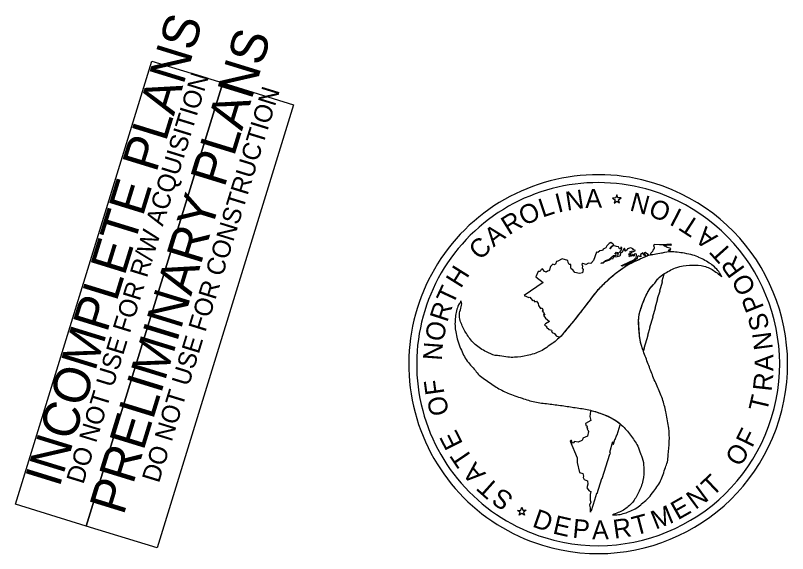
# Model space of a CAD drawing. Extents: x 1347947 to 1350662, y 1027710 to 1030532.
# Drawn here: x 1349312.6 to 1349557.4, y 1030182.8 to 1030353.4 of the extents above; entities that cross this region are included whole.
import ezdxf

# ---------------------------------------------------------------- set-up
doc = ezdxf.new("R2010")
doc.units = 0
for name, color, linetype in [('Old_Level_20', 7, 'Continuous'), ('Sheet Sticker Incomplete CELL', 7, 'Continuous'), ('Sheet Sticker Preliminary CELL', 7, 'Continuous'), ('Sheet Title CELL', 7, 'Continuous')]:
    doc.layers.add(name, color=color, linetype=linetype)

msp = doc.modelspace()

# ---------------------------------------------------------------- linework, layer by layer
at = {"layer": 'Old_Level_20'}
for p, q in [((1349520.2, 1030280.92), (1349517.93, 1030280.66)), ((1349520.59, 1030280.8), (1349520.2, 1030280.92)), ((1349514.56, 1030278.57), (1349513.96, 1030277.91)), ((1349514.68, 1030278.96), (1349514.56, 1030278.57)), ((1349514.95, 1030279.36), (1349514.68, 1030278.96)), ((1349515.06, 1030280.74), (1349514.84, 1030280.22)), ((1349514.84, 1030280.22), (1349515.11, 1030279.99)), ((1349515.06, 1030279.47), (1349514.95, 1030279.36)), ((1349516.78, 1030280.7), (1349515.06, 1030280.74)), ((1349515.12, 1030279.73), (1349515.06, 1030279.47)), ((1349515.11, 1030279.99), (1349515.12, 1030279.73)), ((1349517.93, 1030280.66), (1349516.78, 1030280.7)), ((1349518.12, 1030280.43), (1349518.16, 1030280.56)), ((1349518.21, 1030280.26), (1349518.12, 1030280.43)), ((1349518.16, 1030280.56), (1349520.16, 1030280.71)), ((1349518.65, 1030280.12), (1349518.21, 1030280.26)), ((1349518.85, 1030280.23), (1349518.65, 1030280.12)), ((1349519.03, 1030279.89), (1349518.85, 1030280.23)), ((1349520.33, 1030279.49), (1349519.03, 1030279.89)), ((1349519.63, 1030278.42), (1349519.1, 1030278.33)), ((1349519.5, 1030278.92), (1349520.08, 1030279.23)), ((1349519.85, 1030278.87), (1349519.5, 1030278.92)), ((1349519.99, 1030278.48), (1349519.63, 1030278.42)), ((1349520.14, 1030278.98), (1349519.85, 1030278.87)), ((1349519.99, 1030278.48), (1349520.14, 1030278.98)), ((1349520.08, 1030279.23), (1349520.24, 1030279.21)), ((1349520.16, 1030280.71), (1349520.34, 1030280.56)), ((1349520.24, 1030279.21), (1349520.33, 1030279.49)), ((1349520.34, 1030280.56), (1349520.5, 1030280.52)), ((1349520.5, 1030280.52), (1349520.59, 1030280.8)), ((1349485.87, 1030276.25), (1349484.56, 1030275.49)), ((1349487.76, 1030275.67), (1349485.87, 1030276.25)), ((1349496.77, 1030278.35), (1349495.81, 1030275.69)), ((1349511.75, 1030276.66), (1349510.1, 1030275.9)), ((1349511.56, 1030278.13), (1349510.8, 1030277.6)), ((1349510.8, 1030277.6), (1349510.9, 1030276.83)), ((1349511.68, 1030277.53), (1349511.56, 1030278.13)), ((1349512.39, 1030277.14), (1349511.68, 1030277.53)), ((1349512.41, 1030276.99), (1349511.75, 1030276.66)), ((1349512.19, 1030278.25), (1349511.87, 1030278.12)), ((1349511.87, 1030278.12), (1349512.39, 1030277.14)), ((1349513.29, 1030277.49), (1349512.19, 1030278.25)), ((1349512.41, 1030276.99), (1349512.96, 1030277.2)), ((1349512.95, 1030277.22), (1349513.02, 1030277.45)), ((1349512.96, 1030277.2), (1349512.95, 1030277.22)), ((1349513.02, 1030277.45), (1349513.29, 1030277.49)), ((1349514.05, 1030277.56), (1349513.92, 1030277.4)), ((1349514.13, 1030277.44), (1349513.92, 1030277.4)), ((1349513.96, 1030277.91), (1349514.05, 1030277.56)), ((1349514.63, 1030277.52), (1349514.13, 1030277.44)), ((1349515.18, 1030277.62), (1349514.63, 1030277.52)), ((1349515.65, 1030277.71), (1349515.18, 1030277.62)), ((1349516.23, 1030277.81), (1349515.65, 1030277.71)), ((1349516.85, 1030277.92), (1349516.23, 1030277.81)), ((1349517.63, 1030278.06), (1349516.85, 1030277.92)), ((1349518.37, 1030278.2), (1349517.63, 1030278.06)), ((1349519.1, 1030278.33), (1349518.37, 1030278.2)), ((1349482.24, 1030273.77), (1349481.95, 1030272.75)), ((1349482.96, 1030274.54), (1349482.24, 1030273.77)), ((1349483.5, 1030274.37), (1349482.96, 1030274.54)), ((1349483.8, 1030274.59), (1349483.5, 1030274.37)), ((1349484.09, 1030275.35), (1349483.8, 1030274.59)), ((1349484.56, 1030275.49), (1349484.09, 1030275.35)), ((1349487.82, 1030275.03), (1349487.76, 1030275.67)), ((1349488.13, 1030274.45), (1349487.82, 1030275.03)), ((1349488.68, 1030274.39), (1349488.13, 1030274.45)), ((1349488.65, 1030273.58), (1349488.68, 1030274.39)), ((1349488.8, 1030273.05), (1349488.65, 1030273.58)), ((1349492.48, 1030274.76), (1349492.12, 1030274.5)), ((1349492.12, 1030274.5), (1349492.38, 1030273.88)), ((1349492.38, 1030273.88), (1349492.24, 1030273.24)), ((1349493.16, 1030274.55), (1349492.48, 1030274.76)), ((1349493.36, 1030274.37), (1349493.16, 1030274.55)), ((1349494.3, 1030274.85), (1349493.36, 1030274.37)), ((1349494.99, 1030274.78), (1349494.3, 1030274.85)), ((1349495.81, 1030275.69), (1349494.99, 1030274.78)), ((1349506.64, 1030274.18), (1349505.12, 1030273.22)), ((1349508.75, 1030275.26), (1349506.64, 1030274.18)), ((1349510.1, 1030275.9), (1349508.75, 1030275.26)), ((1349478.3, 1030272.25), (1349477.58, 1030270.55)), ((1349478.93, 1030272.26), (1349478.3, 1030272.25)), ((1349479.24, 1030272.81), (1349478.93, 1030272.26)), ((1349479.71, 1030273.04), (1349479.24, 1030272.81)), ((1349479.91, 1030272.75), (1349479.71, 1030273.04)), ((1349480.15, 1030272.62), (1349479.91, 1030272.75)), ((1349480.13, 1030272.29), (1349480.15, 1030272.62)), ((1349480.8, 1030271.97), (1349480.13, 1030272.29)), ((1349481.3, 1030272.38), (1349480.8, 1030271.97)), ((1349481.7, 1030272.48), (1349481.3, 1030272.38)), ((1349481.95, 1030272.75), (1349481.7, 1030272.48)), ((1349489.32, 1030272.78), (1349488.8, 1030273.05)), ((1349489.97, 1030271.95), (1349489.32, 1030272.78)), ((1349491.4, 1030271.62), (1349489.97, 1030271.95)), ((1349492.33, 1030271.77), (1349491.4, 1030271.62)), ((1349492.24, 1030273.24), (1349492.56, 1030272.89)), ((1349492.56, 1030272.89), (1349492.33, 1030271.77)), ((1349503.05, 1030271.66), (1349500.54, 1030269.54)), ((1349505.12, 1030273.22), (1349503.05, 1030271.66)), ((1349516.82, 1030270.44), (1349517.73, 1030271.15)), ((1349517.62, 1030269.31), (1349518.26, 1030271.41)), ((1349517.73, 1030271.15), (1349518.16, 1030271.44)), ((1349518.15, 1030271.42), (1349518.16, 1030271.44)), ((1349518.26, 1030271.41), (1349518.15, 1030271.42)), ((1349479.91, 1030268.69), (1349473.92, 1030264.58)), ((1349477.58, 1030270.55), (1349479.91, 1030268.69)), ((1349500.54, 1030269.54), (1349498.69, 1030267.86)), ((1349515.3, 1030268.56), (1349515.95, 1030269.49)), ((1349515.95, 1030269.49), (1349516.82, 1030270.44)), ((1349516.87, 1030266.14), (1349517.7, 1030268.95)), ((1349517.73, 1030269.31), (1349517.62, 1030269.31)), ((1349517.63, 1030268.97), (1349517.73, 1030269.31)), ((1349517.7, 1030268.95), (1349517.63, 1030268.97)), ((1349497.35, 1030266.49), (1349495.63, 1030264.4)), ((1349498.69, 1030267.86), (1349497.35, 1030266.49)), ((1349513.19, 1030265.93), (1349513.85, 1030266.93)), ((1349513.85, 1030266.93), (1349514.48, 1030267.64)), ((1349514.48, 1030267.64), (1349515.3, 1030268.56)), ((1349473.92, 1030264.58), (1349475.31, 1030264.01)), ((1349475.31, 1030264.01), (1349475.72, 1030264.05)), ((1349475.72, 1030264.05), (1349476.48, 1030263.02)), ((1349495.63, 1030264.4), (1349493.59, 1030261.74)), ((1349512.03, 1030263.51), (1349512.56, 1030264.68)), ((1349512.56, 1030264.68), (1349513.19, 1030265.93)), ((1349516.19, 1030263.65), (1349516.95, 1030266.11)), ((1349516.95, 1030266.11), (1349516.87, 1030266.14)), ((1349476.48, 1030263.02), (1349476.79, 1030263.1)), ((1349476.79, 1030263.1), (1349477.25, 1030262.56)), ((1349477.25, 1030262.56), (1349477.76, 1030262.83)), ((1349477.76, 1030262.83), (1349478.27, 1030262.08)), ((1349478.27, 1030262.08), (1349478.43, 1030261.49)), ((1349478.43, 1030261.49), (1349479.06, 1030260.5)), ((1349493.59, 1030261.74), (1349491.72, 1030259.29)), ((1349511.04, 1030260.92), (1349511.4, 1030261.93)), ((1349511.4, 1030261.93), (1349512.03, 1030263.51)), ((1349515.4, 1030260.63), (1349516.29, 1030263.62)), ((1349516.29, 1030263.62), (1349516.19, 1030263.65)), ((1349479.06, 1030260.5), (1349479.43, 1030260.69)), ((1349479.43, 1030260.69), (1349479.92, 1030259.98)), ((1349479.92, 1030259.98), (1349479.6, 1030259.76)), ((1349479.6, 1030259.76), (1349479.99, 1030259.19)), ((1349479.99, 1030259.19), (1349480.43, 1030258.49)), ((1349491.72, 1030259.29), (1349490, 1030257.14)), ((1349510.37, 1030258.73), (1349510.66, 1030259.78)), ((1349510.66, 1030259.78), (1349511.04, 1030260.92)), ((1349514.65, 1030257.91), (1349515.48, 1030260.61)), ((1349515.48, 1030260.61), (1349515.4, 1030260.63)), ((1349480.43, 1030258.49), (1349480, 1030258.59)), ((1349480, 1030258.59), (1349480.14, 1030258.21)), ((1349480.14, 1030258.21), (1349480.6, 1030257.47)), ((1349480.6, 1030257.47), (1349481.88, 1030256.37)), ((1349481.88, 1030256.37), (1349480.66, 1030255.63)), ((1349490, 1030257.14), (1349488.28, 1030255)), ((1349510.15, 1030256.8), (1349510.19, 1030257.66)), ((1349510.2, 1030255.89), (1349510.15, 1030256.8)), ((1349510.19, 1030257.66), (1349510.37, 1030258.73)), ((1349513.74, 1030254.59), (1349514.75, 1030257.88)), ((1349514.75, 1030257.88), (1349514.65, 1030257.91)), ((1349480.66, 1030255.63), (1349480.31, 1030255.34)), ((1349480.31, 1030255.34), (1349480.65, 1030254.98)), ((1349480.65, 1030254.98), (1349480.99, 1030254.88)), ((1349480.99, 1030254.88), (1349480.93, 1030254.58)), ((1349480.93, 1030254.58), (1349481.76, 1030253.87)), ((1349488.28, 1030255), (1349486.6, 1030252.96)), ((1349510.26, 1030254.85), (1349510.2, 1030255.89)), ((1349510.32, 1030253.94), (1349510.26, 1030254.85)), ((1349510.38, 1030252.97), (1349510.32, 1030253.94)), ((1349513.07, 1030252.07), (1349513.85, 1030254.58)), ((1349513.85, 1030254.58), (1349513.74, 1030254.59)), ((1349481.76, 1030253.87), (1349482.63, 1030253.64)), ((1349482.63, 1030253.64), (1349482.49, 1030253.37)), ((1349482.49, 1030253.37), (1349482.76, 1030252.88)), ((1349482.76, 1030252.88), (1349483.51, 1030252.54)), ((1349483.51, 1030252.54), (1349484.05, 1030251.81)), ((1349484.05, 1030251.81), (1349484.73, 1030251.51)), ((1349484.73, 1030251.51), (1349484.94, 1030251.17)), ((1349485.55, 1030251.77), (1349484.94, 1030251.17)), ((1349486.6, 1030252.96), (1349485.55, 1030251.77)), ((1349510.46, 1030251.89), (1349510.38, 1030252.97)), ((1349510.6, 1030250.7), (1349510.46, 1030251.89)), ((1349511.92, 1030247.96), (1349513.15, 1030252.04)), ((1349513.15, 1030252.04), (1349513.07, 1030252.07)), ((1349510.8, 1030249.73), (1349510.6, 1030250.7)), ((1349511.05, 1030248.81), (1349510.8, 1030249.73)), ((1349511.4, 1030247.73), (1349511.05, 1030248.81)), ((1349511.69, 1030246.92), (1349511.4, 1030247.73)), ((1349511.69, 1030246.92), (1349512, 1030247.94)), ((1349512, 1030247.94), (1349511.92, 1030247.96)), ((1349494.9, 1030227.92), (1349494.73, 1030226.27)), ((1349495.02, 1030227.85), (1349494.9, 1030227.92)), ((1349495.03, 1030228.21), (1349495.02, 1030227.85)), ((1349495.03, 1030228.21), (1349495.83, 1030228)), ((1349495.83, 1030228), (1349497.05, 1030227.6)), ((1349497.05, 1030227.6), (1349497.89, 1030227.31)), ((1349497.89, 1030227.31), (1349499.34, 1030226.79)), ((1349494.97, 1030225), (1349493.29, 1030224.07)), ((1349494.73, 1030226.27), (1349494.97, 1030225)), ((1349499.34, 1030226.79), (1349500.89, 1030226.09)), ((1349500.89, 1030226.09), (1349502.41, 1030225.27)), ((1349502.41, 1030225.27), (1349503.24, 1030224.74)), ((1349503.24, 1030224.74), (1349504.06, 1030224.13)), ((1349493.29, 1030224.07), (1349493.46, 1030223.51)), ((1349493.46, 1030223.51), (1349493.83, 1030223.16)), ((1349493.83, 1030223.16), (1349493.74, 1030222.77)), ((1349493.74, 1030222.77), (1349493.94, 1030222.48)), ((1349493.94, 1030222.48), (1349493.87, 1030222.19)), ((1349493.87, 1030222.19), (1349494.08, 1030222.04)), ((1349503.31, 1030220.45), (1349504.28, 1030223.61)), ((1349504.06, 1030224.13), (1349504.45, 1030223.8)), ((1349504.28, 1030223.61), (1349504.39, 1030223.58)), ((1349504.39, 1030223.58), (1349504.45, 1030223.8)), ((1349493.9, 1030220.05), (1349492.49, 1030219.35)), ((1349494.22, 1030221.46), (1349493.9, 1030220.05)), ((1349494.08, 1030222.04), (1349494.22, 1030221.46)), ((1349502.76, 1030218.94), (1349503.23, 1030220.47)), ((1349503.23, 1030220.47), (1349503.31, 1030220.45)), ((1349488.62, 1030218.7), (1349488.42, 1030218.42)), ((1349488.42, 1030218.42), (1349490.68, 1030213.12)), ((1349488.92, 1030218.63), (1349488.62, 1030218.7)), ((1349489.1, 1030217.95), (1349488.92, 1030218.63)), ((1349489.44, 1030217.85), (1349489.1, 1030217.95)), ((1349489.82, 1030218.35), (1349489.44, 1030217.85)), ((1349491.01, 1030218.13), (1349489.82, 1030218.35)), ((1349492.14, 1030218.69), (1349491.01, 1030218.13)), ((1349492.32, 1030218.81), (1349492.14, 1030218.69)), ((1349492.49, 1030219.35), (1349492.32, 1030218.81)), ((1349501.91, 1030217.93), (1349502.09, 1030217.5)), ((1349502.09, 1030217.5), (1349502.2, 1030217.49)), ((1349502.2, 1030217.49), (1349502.66, 1030219)), ((1349502.66, 1030219), (1349502.76, 1030218.94)), ((1349490.68, 1030213.12), (1349490.71, 1030211.72)), ((1349490.71, 1030211.72), (1349491.39, 1030208.5)), ((1349491.39, 1030208.5), (1349492.45, 1030208.15)), ((1349492.45, 1030208.15), (1349492.72, 1030207.36)), ((1349492.72, 1030207.36), (1349492.55, 1030206.93)), ((1349492.55, 1030206.93), (1349492.85, 1030206.32)), ((1349492.85, 1030206.32), (1349493.92, 1030205.91)), ((1349493.92, 1030205.91), (1349494.05, 1030204.85)), ((1349494.05, 1030204.85), (1349493.77, 1030203.6)), ((1349493.77, 1030203.6), (1349494.48, 1030202.67)), ((1349494.48, 1030202.67), (1349495.04, 1030202.47)), ((1349494.8, 1030201.58), (1349494.76, 1030199.69)), ((1349495.04, 1030202.47), (1349494.8, 1030201.58)), ((1349495.05, 1030199.06), (1349494.6, 1030198.15)), ((1349494.6, 1030198.15), (1349494.75, 1030197.28)), ((1349494.76, 1030199.69), (1349495.05, 1030199.06)), ((1349494.75, 1030197.28), (1349494.75, 1030196.34)), ((1349494.75, 1030196.34), (1349494.87, 1030195.91))]:
    msp.add_line(p, q, dxfattribs=at)
for points in [[(1349504.16, 1030277.06), (1349503.38, 1030276.85), (1349502.24, 1030276.75), (1349501.84, 1030276.1), (1349501.32, 1030276.24), (1349500.93, 1030275.81), (1349499.37, 1030275.27), (1349498.96, 1030274.86), (1349498.16, 1030274.77), (1349498.44, 1030275.02), (1349498.93, 1030275.04), (1349499.63, 1030275.73), (1349499.97, 1030275.66), (1349500.16, 1030275.88), (1349500.63, 1030275.94), (1349502.15, 1030277.28), (1349502.72, 1030277.31), (1349503.04, 1030277.49), (1349503.39, 1030277.44), (1349503.83, 1030277.59), (1349503.6, 1030277.94), (1349503.16, 1030278.08), (1349502.59, 1030277.77), (1349503.19, 1030278.35), (1349503.86, 1030278.12), (1349504.73, 1030279.13), (1349504.88, 1030279.88), (1349504.54, 1030279.9), (1349504.4, 1030279.43), (1349504.11, 1030279.41), (1349503.73, 1030280.01), (1349503.16, 1030280.1), (1349502.54, 1030280.31), (1349501.77, 1030280.21), (1349501.05, 1030279.44), (1349501.65, 1030280.28), (1349502.29, 1030280.68), (1349501.8, 1030281.05), (1349501.32, 1030281.43), (1349500.81, 1030281.05), (1349500.07, 1030280.31), (1349499.8, 1030279.71), (1349498.91, 1030279.3), (1349498.78, 1030278.98), (1349498.54, 1030278.85), (1349497.84, 1030278.78), (1349497.23, 1030278.2), (1349496.77, 1030278.35)], [(1349510.9, 1030276.83), (1349510, 1030277.22), (1349509.84, 1030276.99), (1349509.75, 1030276.31), (1349508.69, 1030275.47), (1349505.8, 1030274.2), (1349505.3, 1030274.13), (1349505.06, 1030273.92), (1349504.68, 1030273.98), (1349504.68, 1030274.15), (1349505.24, 1030274.32), (1349508.62, 1030275.97), (1349509.03, 1030276.3), (1349509.34, 1030276.29), (1349509.45, 1030277.73), (1349509.05, 1030277.83), (1349508.78, 1030277.68), (1349508.75, 1030277.24), (1349508.4, 1030277.12), (1349508.39, 1030277.63), (1349507.79, 1030277.05), (1349507.1, 1030276.95), (1349507.65, 1030277.35), (1349507.79, 1030277.7), (1349507.4, 1030277.74), (1349507.08, 1030277.44), (1349507.28, 1030278), (1349507.6, 1030278.02), (1349508.11, 1030278.29), (1349507.38, 1030278.48), (1349507.85, 1030278.62), (1349508.29, 1030278.49), (1349509.16, 1030278.93), (1349508.68, 1030279.11), (1349508.33, 1030278.99), (1349508.45, 1030279.38), (1349507.58, 1030279.7), (1349506.67, 1030279.41), (1349506.54, 1030279.08), (1349506.03, 1030278.64), (1349505.75, 1030278.82), (1349505.85, 1030279.15), (1349505.68, 1030279.63), (1349505.23, 1030279.09), (1349504.96, 1030278.29), (1349504.56, 1030278.27), (1349504.16, 1030277.06)], [(1349494.87, 1030195.91), (1349495.05, 1030196.48), (1349495.18, 1030196.44), (1349496.23, 1030199.86), (1349496.3, 1030199.81), (1349496.95, 1030201.91), (1349497.05, 1030201.88), (1349498.52, 1030206.65), (1349498.62, 1030206.62), (1349501.01, 1030214.37), (1349501.11, 1030214.31), (1349501.23, 1030214.73), (1349501.13, 1030214.76), (1349501.16, 1030214.86), (1349500.98, 1030214.92), (1349502.02, 1030218.29)]]:
    msp.add_lwpolyline(points, dxfattribs=at)
at = {"layer": 'Sheet Sticker Incomplete CELL'}
msp.add_lwpolyline([(1349335.04, 1030191.51), (1349312.58, 1030198.42), (1349355.85, 1030338.91), (1349378.3, 1030332)], close=True, dxfattribs=at)
at = {"layer": 'Sheet Sticker Preliminary CELL'}
msp.add_lwpolyline([(1349357.5, 1030184.59), (1349335.04, 1030191.51), (1349378.3, 1030332), (1349400.76, 1030325.08)], close=True, dxfattribs=at)
at = {"layer": 'Sheet Title CELL'}
for p, q in [((1349515, 1030300.24), (1349515, 1030300.24)), ((1349502.94, 1030295.54), (1349501.92, 1030295.48)), ((1349503.2, 1030296.52), (1349502.94, 1030295.54)), ((1349503.57, 1030295.53), (1349503.2, 1030296.52)), ((1349504.61, 1030295.53), (1349503.57, 1030295.53)), ((1349503.79, 1030294.91), (1349504.61, 1030295.53)), ((1349501.92, 1030295.48), (1349502.74, 1030294.89)), ((1349502.74, 1030294.89), (1349502.44, 1030293.91)), ((1349502.44, 1030293.91), (1349503.27, 1030294.55)), ((1349503.27, 1030294.55), (1349504.13, 1030293.96)), ((1349504.13, 1030293.96), (1349503.79, 1030294.91)), ((1349453.75, 1030262.95), (1349453.84, 1030262.81)), ((1349453.75, 1030262.95), (1349453.84, 1030262.81)), ((1349471.76, 1030196.5), (1349472.79, 1030196.55)), ((1349472.6, 1030195.94), (1349471.76, 1030196.5)), ((1349472.29, 1030194.94), (1349472.6, 1030195.94)), ((1349473.13, 1030195.55), (1349472.29, 1030194.94)), ((1349472.79, 1030196.55), (1349473.09, 1030197.54)), ((1349473.09, 1030197.54), (1349473.43, 1030196.54)), ((1349473.99, 1030194.97), (1349473.13, 1030195.55)), ((1349473.43, 1030196.54), (1349474.48, 1030196.55)), ((1349474.48, 1030196.55), (1349473.63, 1030195.92)), ((1349473.63, 1030195.92), (1349473.99, 1030194.97))]:
    msp.add_line(p, q, dxfattribs=at)
for radius, start, end in [(60.05, 72.8711, 252.8711), (57.54, 72.8711, 252.8711), (60.05, 252.8711, 72.8711), (57.54, 252.8711, 72.8711)]:
    msp.add_arc((1349497.33, 1030242.86), radius, start, end, dxfattribs=at)
for points in [[(1349536.49, 1030270.6), (1349535.84, 1030271.77), (1349533.01, 1030274.61), (1349529.3, 1030276.71), (1349528.92, 1030276.88), (1349526.74, 1030277.59), (1349524.08, 1030278.09), (1349519.62, 1030278.42), (1349515.16, 1030277.62), (1349513.29, 1030277.28), (1349511.3, 1030276.44), (1349507.31, 1030274.55), (1349503.84, 1030272.28), (1349500.17, 1030269.2), (1349497.16, 1030266.28), (1349494.43, 1030262.85), (1349491.8, 1030259.38), (1349489.16, 1030256.09), (1349486.35, 1030252.66), (1349483.24, 1030249.76), (1349482.93, 1030249.54), (1349479.04, 1030246.94), (1349474.84, 1030245.59), (1349470.78, 1030245.02), (1349468.72, 1030245.06), (1349466.18, 1030245.47), (1349464.71, 1030245.64), (1349461.88, 1030246.74), (1349458.34, 1030249.09), (1349455.81, 1030252.16), (1349454.07, 1030255.4), (1349453.41, 1030259.09), (1349453.84, 1030262.81), (1349453.75, 1030262.95)], [(1349501.87, 1030195.09), (1349503.29, 1030195.1), (1349507.15, 1030196.13), (1349510.83, 1030198.28), (1349511.1, 1030198.55), (1349512.89, 1030200.06), (1349514.59, 1030202.11), (1349517.12, 1030205.83), (1349518.65, 1030210.06), (1349519.29, 1030211.85), (1349519.56, 1030214.06), (1349519.89, 1030218.39), (1349519.69, 1030222.51), (1349518.87, 1030227.27), (1349517.86, 1030231.31), (1349516.23, 1030235.39), (1349514.51, 1030239.42), (1349513, 1030243.39), (1349511.48, 1030247.48), (1349510.48, 1030251.65), (1349510.44, 1030252.09), (1349510.16, 1030256.72), (1349511.06, 1030260.99), (1349512.6, 1030264.76), (1349513.65, 1030266.65), (1349515.29, 1030268.55), (1349516.18, 1030269.78), (1349518.53, 1030271.68), (1349522.32, 1030273.51), (1349526.25, 1030274.2), (1349529.97, 1030274.1), (1349533.47, 1030272.83), (1349536.49, 1030270.6)], [(1349453.84, 1030262.81), (1349453.1, 1030261.62), (1349452.08, 1030257.77), (1349452.12, 1030253.51), (1349452.2, 1030253.11), (1349452.63, 1030250.85), (1349453.52, 1030248.32), (1349455.51, 1030244.3), (1349458.4, 1030240.81), (1349459.65, 1030239.38), (1349461.34, 1030238.09), (1349464.99, 1030235.57), (1349468.7, 1030233.7), (1349473.2, 1030232.04), (1349477.23, 1030230.87), (1349481.54, 1030230.27), (1349485.89, 1030229.71), (1349490.09, 1030229.07), (1349494.39, 1030228.35), (1349498.5, 1030227.11), (1349498.85, 1030226.98), (1349503, 1030224.9), (1349506.28, 1030221.95), (1349508.79, 1030218.68), (1349509.86, 1030216.88), (1349510.76, 1030214.5), (1349511.29, 1030213.14), (1349511.82, 1030210.13), (1349511.52, 1030205.92), (1349510.12, 1030202.15), (1349508.2, 1030199.01), (1349505.36, 1030196.61), (1349501.87, 1030195.09)]]:
    msp.add_spline(points, degree=3, dxfattribs=at)

# ---------------------------------------------------------------- texts
at = {"layer": 'Sheet Sticker Incomplete CELL'}
for s, height, p in [('INCOMPLETE PLANS', 11.52, (1349326.49, 1030203.5)), ('DO NOT USE FOR R/W ACQUISITION', 5.76, (1349334.09, 1030204.56))]:
    msp.add_text(s, height=height, rotation=72.8834, dxfattribs=at).set_placement(p)
at = {"layer": 'Sheet Sticker Preliminary CELL'}
for s, height, p in [('PRELIMINARY PLANS', 11.52, (1349346.84, 1030194.67)), ('DO NOT USE FOR CONSTRUCTION', 5.76, (1349358.06, 1030204.93))]:
    msp.add_text(s, height=height, rotation=72.8834, dxfattribs=at).set_placement(p)
at = {"layer": 'Sheet Title CELL'}
for s, height, rotation, p in [('N', 5.98, 8.7664, (1349487.44, 1030291.49)), ('A', 5.99, 1.3345, (1349493.26, 1030292.34)), ('I', 6, 14.4665, (1349484.6, 1030290.8)), ('N', 5.99, 165.0792, (1349514.2, 1030295.93)), ('O', 6, 24.6896, (1349473.87, 1030286.6)), ('L', 5.97, 18.4559, (1349479.66, 1030289.27)), ('O', 5.97, 157.8312, (1349520.92, 1030293.26)), ('R', 5.98, 31.8092, (1349468.99, 1030283.6)), ('I', 6, 152.6956, (1349524.35, 1030291.53)), ('T', 5.98, 147.0457, (1349530.04, 1030287.88)), ('A', 5.98, 38.1731, (1349464.17, 1030279.79)), ('A', 6, 139.9613, (1349535.53, 1030283.37)), ('C', 5.97, 45.6702, (1349459.97, 1030275.54)), ('T', 5.97, 131.8742, (1349540.14, 1030278.4)), ('R', 6, 125.7744, (1349544.08, 1030273.06)), ('H', 5.98, 58.0125, (1349453.77, 1030266.65)), ('O', 6, 118.5853, (1349547.59, 1030266.73)), ('T', 6, 65.0972, (1349451.26, 1030261.35)), ('P', 5.98, 111.8933, (1349550.02, 1030260.8)), ('R', 5.99, 71.7469, (1349449.47, 1030255.9)), ('S', 5.96, 104.7015, (1349551.74, 1030254.41)), ('O', 6, 78.3568, (1349448.19, 1030249.71)), ('N', 5.97, 97.491, (1349552.75, 1030247.71)), ('N', 5.99, 85.8549, (1349447.74, 1030243.87)), ('A', 5.97, 90.4594, (1349552.92, 1030240.64)), ('R', 5.99, 83.7063, (1349552.28, 1030234.05)), ('F', 6, 97.9418, (1349448.62, 1030233.49)), ('O', 5.99, 105.0887, (1349450.23, 1030227.36)), ('T', 5.97, 76.7496, (1349550.8, 1030227.43)), ('E', 5.97, 117.028, (1349454.58, 1030217.68)), ('F', 5.98, 63.8404, (1349546.12, 1030216.12)), ('O', 5.98, 56.6752, (1349542.23, 1030210.02)), ('T', 5.97, 124.1437, (1349457.85, 1030212.82)), ('A', 6.01, 131.1989, (1349461.93, 1030208.15)), ('T', 5.98, 43.3715, (1349533.55, 1030200.64)), ('T', 6, 138.2512, (1349466.24, 1030204.2)), ('S', 5.98, 144.6274, (1349470.88, 1030200.88)), ('N', 6, 36.5295, (1349528.16, 1030196.57)), ('E', 5.97, 29.558, (1349522.58, 1030193.31)), ('M', 5.97, 22.0912, (1349515.57, 1030190.33)), ('D', 5.99, 340.7241, (1349476.16, 1030191.43)), ('T', 5.98, 14.8561, (1349509.02, 1030188.5)), ('E', 5.96, 347.012, (1349482.67, 1030189.22)), ('P', 5.99, 354.5444, (1349489.03, 1030187.88)), ('A', 5.98, 1.137, (1349495.4, 1030187.27)), ('R', 5.99, 8.2056, (1349502.49, 1030187.49))]:
    msp.add_text(s, height=height, rotation=rotation, dxfattribs=at).set_placement(p)

doc.saveas('drawing.dxf')
